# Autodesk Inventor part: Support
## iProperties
Shininess: 20.0
Angle Display Precision: 2
Document Length Units: 11269
Document Angle Units: 11279
Document Time Units: 11290
Document Mass Units: 11283
Document Length Units Precision: 3
Document Angle Units Precision: 2
Created: 2002-09
Part Number: Support
Material: Par défaut
Document SubType Name: Modélisation
Designer: administrateur
Density: 0.0
Volumn: 0.0
Area: 0.0
PropertySet Name: Model Information
Control State: 0
Master: False
Checked Out: False
Author: administrateur
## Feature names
1. Extrusion1
2. Extrusion2
3. Extrusion3
4. Extrusion4
5. Extrusion5
6. Extrusion6
7. Extrusion7
8. Extrusion8
9. Extrusion9
10. Extrusion10
11. Extrusion11
12. Extrusion12
13. Congé1 [Fillet]
14. Congé2 [Fillet]
15. Extrusion13
16. Extrusion14
17. Extrusion15
18. Extrusion16
